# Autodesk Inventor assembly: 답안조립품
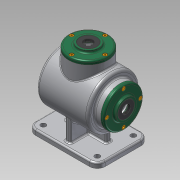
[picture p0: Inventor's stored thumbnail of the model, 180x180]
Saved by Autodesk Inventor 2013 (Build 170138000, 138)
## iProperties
Created: 2016-09
Part Number: 답안조립품
Document SubType Name: Assembly
Designer: default
Author: default
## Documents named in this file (6)
- C:\Documents and Settings\default\바탕 화면\460908V1011\답안조립품.iam
- C:\Documents and Settings\default\바탕 화면\460908V1011\1.본체.ipt
- C:\Documents and Settings\default\바탕 화면\460908V1011\커버.ipt
- C:\Documents and Settings\default\바탕 화면\460908V1011\오일실 17 32 8.ipt
- C:\Documents and Settings\default\바탕 화면\460908V1011\베어링 6203.ipt
- C:\Documents and Settings\default\바탕 화면\460908V1011\M4.ipt
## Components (9 placed, 2 different names)
1. 1.본체:1
2. M4:1
3. M4:3
4. M4:4
5. M4:5
6. M4:2
7. M4:6
8. M4:7
9. M4:8
